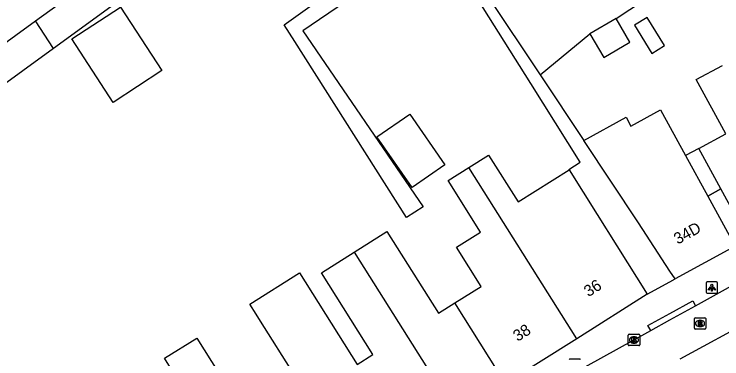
# Model space of a CAD drawing. Extents: x 161801 to 162379, y 382315 to 382832.
# Drawn here: x 161942.5 to 162004.5, y 382535.4 to 382565.6 of the extents above; entities that cross this region are included whole.
import ezdxf

# ---------------------------------------------------------------- set-up
doc = ezdxf.new("R2010")
doc.units = 0
for name, color, linetype in [('IMGEO_Brandkraan', 7, 'Continuous'), ('IMGEO_Groenvoorziening', 7, 'Continuous'), ('IMGEO_Kolk', 7, 'Continuous'), ('IMGEO_Lichtpunt', 7, 'Continuous'), ('IMGEO_Pand', 7, 'Continuous'), ('IMGEO_Pand_nummerreeks', 7, 'Continuous'), ('IMGEO_Pand_overbouw', 7, 'Continuous'), ('IMGEO_Rijbaan_lokaal_open', 7, 'Continuous'), ('IMGEO_Rioolput', 7, 'Continuous'), ('IMGEO_Voetpad_open', 7, 'Continuous')]:
    doc.layers.add(name, color=color, linetype=linetype)

msp = doc.modelspace()

# ---------------------------------------------------------------- linework, layer by layer
at = {"layer": 'IMGEO_Brandkraan'}
msp.add_line((161991.231, 382535.405), (161992.083, 382535.405), dxfattribs=at)
msp.add_lwpolyline([(161991.231, 382535.405), (161992.083, 382535.405)], dxfattribs=at)
for centre, start, end in [((161991.233, 382535.329), 91.55205, 178.44795), ((161991.233, 382535.329), 91.55205, 178.44795), ((161992.081, 382535.329), 1.55205, 88.44795), ((161992.081, 382535.329), 1.55205, 88.44795)]:
    msp.add_arc(centre, 0.0765, start, end, dxfattribs=at)
at = {"layer": 'IMGEO_Groenvoorziening'}
for points in [[(161995.273, 382565.225), (162000, 382568.349), (162005.088, 382571.967)], [(161988.628, 382560.283), (161992.973, 382563.87)]]:
    msp.add_lwpolyline(points, dxfattribs=at)
at = {"layer": 'IMGEO_Kolk'}
for p, q in [((161996.346, 382536.636), (161996.346, 382537.488)), ((161996.421, 382537.562), (161997.273, 382537.562)), ((161996.834, 382537.342), (161996.859, 382537.342)), ((161997.347, 382537.488), (161997.347, 382536.636)), ((161996.857, 382536.782), (161996.832, 382536.782)), ((161997.273, 382536.562), (161996.421, 382536.562))]:
    msp.add_line(p, q, dxfattribs=at)
for points in [[(161996.346, 382536.636), (161996.346, 382537.488)], [(161996.421, 382537.562), (161997.273, 382537.562)], [(161997.347, 382537.488), (161997.347, 382536.636)], [(161996.667, 382537.262), (161996.79, 382537.262), (161996.79, 382537.111), (161996.92, 382537.262), (161997.084, 382537.262), (161996.938, 382537.111), (161997.091, 382536.862), (161996.939, 382536.862), (161996.854, 382537.026), (161996.79, 382536.959), (161996.79, 382536.862), (161996.667, 382536.862), (161996.667, 382537.262)], [(161997.273, 382536.562), (161996.421, 382536.562)]]:
    msp.add_lwpolyline(points, dxfattribs=at)
for centre, start, end in [((161996.423, 382537.486), 91.55205, 178.44795), ((161996.423, 382537.486), 91.55205, 178.44795), ((161997.271, 382537.486), 1.55205, 88.44795), ((161997.271, 382537.486), 1.55205, 88.44795), ((161996.423, 382536.638), 181.55205, 268.44795), ((161996.423, 382536.638), 181.55205, 268.44795), ((161997.271, 382536.638), 271.55205, 358.44795), ((161997.271, 382536.638), 271.55205, 358.44795)]:
    msp.add_arc(centre, 0.0765, start, end, dxfattribs=at)
for centre, major_axis, ratio, start_param, end_param in [((161996.833, 382537.062), (-0.387, 0.002), 0.722429, 4.712389, 7.853982), ((161996.858, 382537.062), (-0.39, 0.002), 0.717154, 1.570796, 4.712389)]:
    msp.add_ellipse(centre, major_axis=major_axis, ratio=ratio, start_param=start_param, end_param=end_param, dxfattribs=at)
at = {"layer": 'IMGEO_Lichtpunt'}
for p, q in [((162003.171, 382542.048), (162003.171, 382541.241)), ((162003.171, 382542.048), (162003.171, 382541.241)), ((162004.073, 382542.143), (162003.265, 382542.143)), ((162004.073, 382542.143), (162003.265, 382542.143)), ((162004.167, 382541.241), (162004.167, 382542.048)), ((162004.167, 382541.241), (162004.167, 382542.048)), ((162003.265, 382541.147), (162004.073, 382541.147)), ((162003.265, 382541.147), (162004.073, 382541.147))]:
    msp.add_line(p, q, dxfattribs=at)
for points in [[(162003.545, 382541.712), (162003.584, 382541.684), (162003.396, 382541.422), (162003.358, 382541.449), (162003.545, 382541.712)], [(162003.647, 382541.664), (162003.694, 382541.664), (162003.694, 382541.342), (162003.647, 382541.342), (162003.647, 382541.664)], [(162003.757, 382541.684), (162003.795, 382541.711), (162003.982, 382541.449), (162003.943, 382541.421), (162003.757, 382541.684)]]:
    msp.add_lwpolyline(points, dxfattribs=at)
msp.add_circle((162003.67, 382541.846), 0.0994, dxfattribs=at)
for centre, start, end in [((162003.265, 382542.048), 90, 180), ((162003.265, 382542.048), 90, 180), ((162004.073, 382542.048), 0, 90), ((162004.073, 382542.048), 0, 90), ((162003.265, 382541.241), 180, 270), ((162003.265, 382541.241), 180, 270), ((162004.073, 382541.241), 270, 0), ((162004.073, 382541.241), 270, 360)]:
    msp.add_arc(centre, 0.0946, start, end, dxfattribs=at)
at = {"layer": 'IMGEO_Pand'}
for points in [[(161944.377, 382565.031), (161949.608, 382568.813), (161951.303, 382566.468), (161945.946, 382562.594)], [(161951.179, 382557.869), (161947.547, 382563.429), (161951.82, 382566.221), (161955.452, 382560.66), (161951.179, 382557.869)], [(161995.273, 382565.225), (161992.973, 382563.87)], [(161992.973, 382563.87), (161994.193, 382561.798), (161996.494, 382563.153), (161995.273, 382565.225)], [(161996.897, 382564.632), (161998.414, 382562.17), (161999.516, 382562.849), (161998, 382565.311), (161996.897, 382564.632)], [(161945.946, 382562.594), (161940.543, 382558.688), (161938.848, 382561.033), (161944.377, 382565.031)], [(161945.946, 382562.594), (161944.377, 382565.031)], [(162006.849, 382545.908), (162004.456, 382550.299), (162002.526, 382553.841), (162004.896, 382555.133), (162002.307, 382559.877), (162004.598, 382561.119)], [(161992.434, 382554.55), (161996.148, 382556.578), (161996.58, 382555.789), (161999.177, 382557.208), (162001.369, 382553.207), (162003.31, 382549.666), (162005.707, 382545.278)], [(161974.303, 382554.846), (161977.184, 382556.845), (161980.265, 382552.406), (161977.384, 382550.407), (161974.303, 382554.846)], [(162000.442, 382542.402), (162000, 382543.083), (161997.253, 382547.318), (161992.434, 382554.55)], [(161982.375, 382552.182), (161984.094, 382553.265), (161986.687, 382549.148), (161991.153, 382551.961)], [(161981.145, 382540.302), (161983.448, 382541.752), (161981.292, 382545.176), (161983.392, 382546.498), (161980.54, 382551.026), (161982.375, 382552.182)], [(161991.824, 382537.171), (161982.375, 382552.182)], [(161991.153, 382551.961), (161993.614, 382548.054), (161995.349, 382545.3), (161998.013, 382541.069)], [(161972.324, 382544.765), (161975.185, 382546.567), (161979.703, 382539.393), (161981.145, 382540.302)], [(161972.576, 382534.922), (161973.948, 382535.786), (161969.438, 382542.947), (161972.324, 382544.765)], [(161972.324, 382544.765), (161981.283, 382530.533)], [(162005.707, 382545.278), (162000.442, 382542.402)], [(161972.67, 382525.109), (161970, 382529.349), (161964.109, 382538.701), (161963.728, 382539.307), (161963.163, 382540.205), (161967.521, 382542.95), (161972.576, 382534.922)], [(161998.013, 382541.069), (161991.824, 382537.171)], [(161985.588, 382533.244), (161981.145, 382540.302)], [(161957.403, 382532.702), (161955.683, 382535.455), (161958.521, 382537.228), (161962.218, 382531.312), (161962.454, 382530.934), (161962.501, 382530.857), (161960.218, 382529.43)], [(161991.824, 382537.171), (161985.588, 382533.244)]]:
    msp.add_lwpolyline(points, dxfattribs=at)
at = {"layer": 'IMGEO_Pand_overbouw'}
for points in [[(162003.31, 382549.666), (162004.456, 382550.299), (162002.526, 382553.841), (162001.369, 382553.207)], [(162006.849, 382545.908), (162004.456, 382550.299), (162003.31, 382549.666), (162005.707, 382545.278)]]:
    msp.add_lwpolyline(points, close=True, dxfattribs=at)
at = {"layer": 'IMGEO_Rijbaan_lokaal_open'}
for points in [[(162002.236, 382540.051), (162005.658, 382541.95)], [(161998.314, 382537.876), (162000, 382538.811), (162002.236, 382540.051)], [(162007.323, 382538.877), (162000.874, 382535.365)], [(161948.095, 382507.457), (161949.145, 382508.117), (161953.15, 382510.607), (161979.276, 382527.063), (161985.491, 382530.651), (161991.203, 382533.931), (161998.314, 382537.876)]]:
    msp.add_lwpolyline(points, dxfattribs=at)
at = {"layer": 'IMGEO_Rioolput'}
for p, q in [((162002.138, 382538.079), (162002.138, 382538.931)), ((162002.213, 382539.005), (162003.065, 382539.005)), ((162002.626, 382538.785), (162002.651, 382538.785)), ((162003.139, 382538.931), (162003.139, 382538.079)), ((162003.065, 382538.005), (162002.213, 382538.005)), ((162002.649, 382538.225), (162002.624, 382538.225))]:
    msp.add_line(p, q, dxfattribs=at)
for points in [[(162002.138, 382538.079), (162002.138, 382538.931)], [(162002.213, 382539.005), (162003.065, 382539.005)], [(162002.727, 382538.703), (162002.475, 382538.705), (162002.475, 382538.305)], [(162002.653, 382538.624), (162002.599, 382538.624), (162002.599, 382538.543)], [(162002.599, 382538.543), (162002.651, 382538.543)], [(162003.139, 382538.931), (162003.139, 382538.079)], [(162003.065, 382538.005), (162002.213, 382538.005)], [(162002.475, 382538.305), (162002.599, 382538.305), (162002.599, 382538.467), (162002.61, 382538.467)], [(162002.657, 382538.438), (162002.728, 382538.305), (162002.868, 382538.305), (162002.803, 382538.431)]]:
    msp.add_lwpolyline(points, dxfattribs=at)
for centre, radius, start, end in [((162002.215, 382538.929), 0.0765, 91.55205, 178.44795), ((162002.215, 382538.929), 0.0765, 91.55205, 178.44795), ((162002.635, 382538.732), 0.19, 274.7715, 282.96867), ((162002.659, 382538.528), 0.0964, 77.00612, 93.18647), ((162002.673, 382538.585), 0.0378, 276.66336, 79.67722), ((162002.726, 382538.593), 0.109, 350.36119, 89.41601), ((162002.724, 382538.593), 0.112, 277.58423, 350.98172), ((162003.063, 382538.929), 0.0765, 1.55205, 88.44795), ((162003.063, 382538.929), 0.0765, 1.55205, 88.44795), ((162002.215, 382538.081), 0.0765, 181.55205, 268.44795), ((162002.215, 382538.081), 0.0765, 181.55205, 268.44795), ((162002.609, 382538.414), 0.0533, 26.02933, 88.69889), ((162002.708, 382538.378), 0.108, 29.51342, 73.79051), ((162003.063, 382538.081), 0.0765, 271.55205, 358.44795), ((162003.063, 382538.081), 0.0765, 271.55205, 358.44795)]:
    msp.add_arc(centre, radius, start, end, dxfattribs=at)
for centre, major_axis, ratio, start_param, end_param in [((162002.625, 382538.505), (-0.387, 0.002), 0.722429, 4.712389, 7.853982), ((162002.65, 382538.505), (-0.39, 0.002), 0.717154, 1.570796, 4.712389)]:
    msp.add_ellipse(centre, major_axis=major_axis, ratio=ratio, start_param=start_param, end_param=end_param, dxfattribs=at)
at = {"layer": 'IMGEO_Voetpad_open'}
for points in [[(161991.153, 382551.961), (161991.121, 382552.009), (161992.14, 382552.651), (161987.811, 382559.519), (161983.621, 382566.165), (161979.755, 382572.298), (161967.811, 382564.144), (161978.347, 382548.711), (161976.906, 382547.794), (161967.106, 382563.196), (161966.173, 382564.661), (161979.378, 382574.126)], [(161979.378, 382574.126), (161988.628, 382560.283)], [(161988.628, 382560.283), (161992.434, 382554.55)], [(161998.013, 382541.069), (162000, 382542.159), (162000.442, 382542.402)], [(161998.314, 382537.876), (161998.072, 382538.312), (162000, 382539.382), (162001.994, 382540.488), (162002.236, 382540.051)]]:
    msp.add_lwpolyline(points, dxfattribs=at)

# ---------------------------------------------------------------- texts
at = {"layer": 'IMGEO_Pand_nummerreeks'}
for s, rotation, p in [('34D', 28.64552, (162000.676, 382545.401)), ('36', 32.20023, (161992.85, 382540.795)), ('38', 32.20081, (161986.64, 382536.885))]:
    msp.add_text(s, height=1, rotation=rotation, dxfattribs=at).set_placement(p)

doc.saveas('drawing.dxf')
